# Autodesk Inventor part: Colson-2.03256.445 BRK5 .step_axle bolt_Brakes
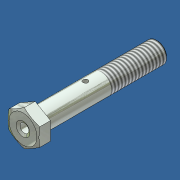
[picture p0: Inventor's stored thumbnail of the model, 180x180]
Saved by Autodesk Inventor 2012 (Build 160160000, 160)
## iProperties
Created: 2010-10
Part Number: Colson-2.03256.445 BRK5 .step_axle bolt_Brakes
Document SubType Name: Modeling
Designer: Administrator
Density: 7.85 g/cm^3
Material: Steel
Mass: 36.0236 g
Surface Area: 26.8767 cm^2
Volume: 4.589 cm^3
Author: Administrator
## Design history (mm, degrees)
feature "Base1"
thread "Thread1" dims "d0" = 25.4, "d1" = 0
body "Solid1"
